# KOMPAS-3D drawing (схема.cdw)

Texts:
  Технологическая схема сборки
  Текст на чертеже
  Размерные надписи
  Шероховатость
  Линия-выноска #1
  Линия-выноска #2
  Линия-выноска #3
  Отклонения формы и база
  Заголовок таблицы
  Ячейка таблицы
  Стрелка вида
  Обозначение изменения
  Фигурная скобка
  Номер узла
  Марка координационной оси
  VRCB
  Выносная надпись
  Обозначение узла
  Марка/позиционное обозначение с линией-выноской
  Марка/позиционное обозначение на линии
  Марка/позиционное обозначение без линии-выноски
  Картер
  Распорная втулка
  Прокладка
  регулировочая
  Крышка
  Уплотнитель
  Рейка
  Упор рейки
  Подпятник
  Стопорная гайка
  Втулка рейки
  Механизм рулевого
  управления в сборе
  Подшипник
  Шестерня в сборе
  Шестерня
  Болт с шайбой
  Шайба
  Болт
  Запресовать
  Пробка с пружиной
  Пробка
  Пружина
  Пр. чехол с хомутом
  Правый чехол
  Хомут
  Лев. чехол с хомутом
  Левый чехол
  Сапун
  Технологическая
  схема сборки
Dimensions and other numbers on the sheet: 7; 1; 32; 34,35,36; 3; 33; 2; 20; 10; 11; 18; 30; 49; 0; 15; 40; 48; 17; 12; 21; 5, 55; 56; 22; 4; 5; 6; 8; 9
